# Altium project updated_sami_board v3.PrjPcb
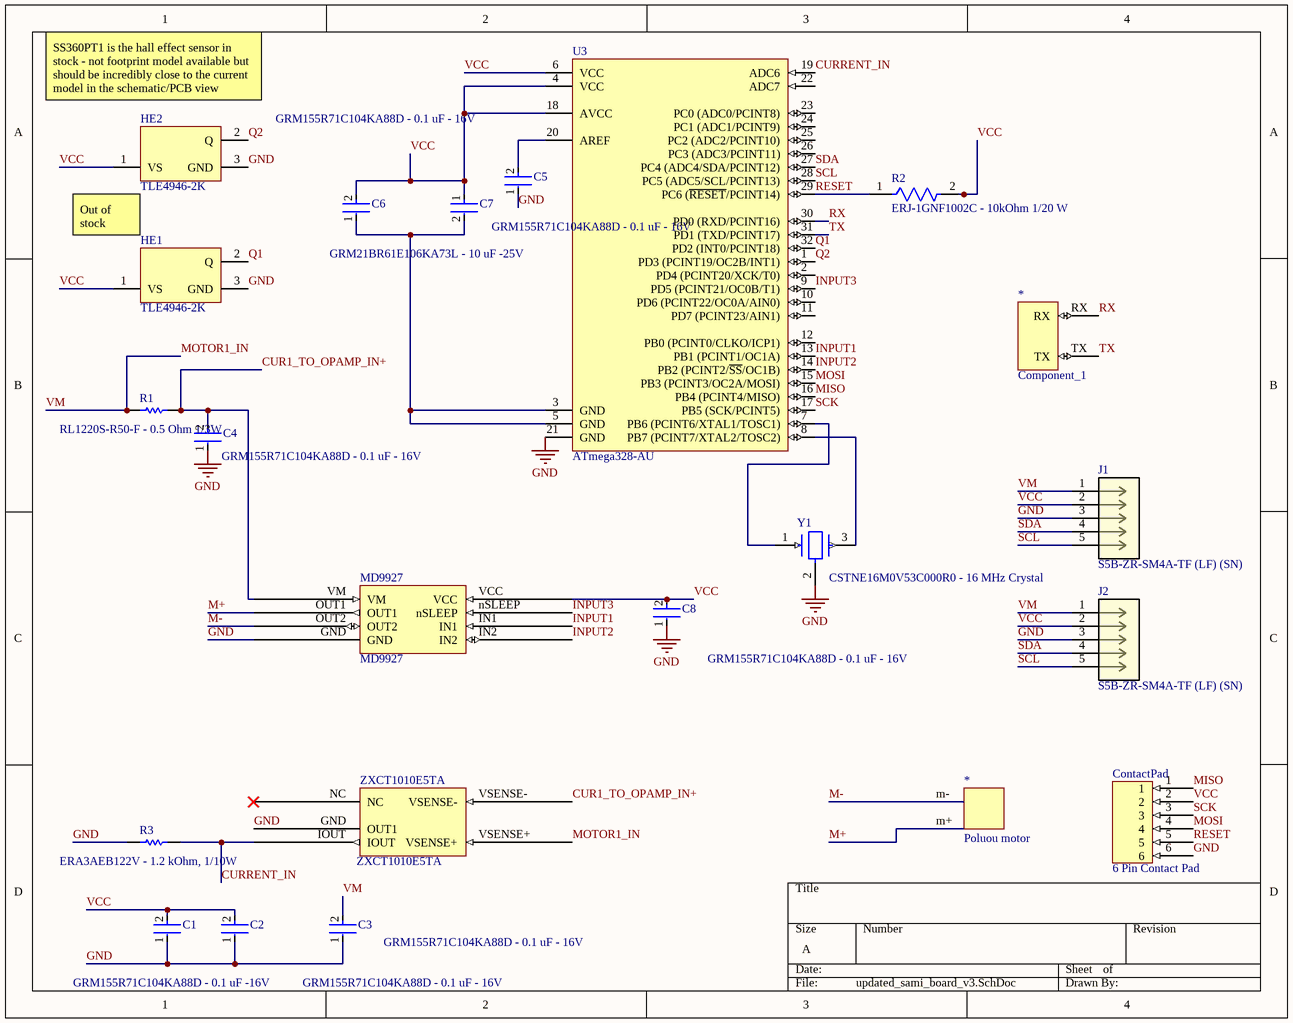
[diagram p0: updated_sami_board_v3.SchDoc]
1 sheet, 22 parts. Net scope: global (net labels, ports and power ports of the same name join across sheets).
Board files: sami_updated_v2.PcbDoc, sami_updated_v3.PcbDoc

## Sheet updated_sami_board_v3.SchDoc
size A; SheetNumber: 1; SheetTotal: 1

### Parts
(Parts that share a designator on the sheet are numbered #1, #2 ... from top to bottom, then left to right.)
*#1  Component_1  [UART Header Pins]
*#2  Poluou motor  [PCBComponent_1]
C1  GRM155R71C104KA88D - 0.1 uF -16V  [FP-GRM15-MFG]
C2  GRM155R71C104KA88D - 0.1 uF - 16V  [FP-GRM15-MFG]
C3  GRM155R71C104KA88D - 0.1 uF - 16V  [FP-GRM15-MFG]
C4  GRM155R71C104KA88D - 0.1 uF - 16V  [FP-GRM15-MFG]
C5  GRM155R71C104KA88D - 0.1 uF - 16V  [FP-GRM15-MFG]
C6  GRM155R71C104KA88D - 0.1 uF - 16V  [FP-GRM15-MFG]
C7  GRM21BR61E106KA73L - 10 uF -25V  [FP-GRM21B-0_15-IPC_C]
C8  GRM155R71C104KA88D - 0.1 uF - 16V  [FP-GRM15-MFG]
ContactPad  6 Pin Contact Pad  [6PinContactPad]
HE1  TLE4946-2K  [INF-PG-SC59_M]
HE2  TLE4946-2K  [INF-PG-SC59_M]
J1  S5B-ZR-SM4A-TF (LF) (SN)  [CONN_S5B-ZR-SM4A-TF_JST]
J2  S5B-ZR-SM4A-TF (LF) (SN)  [CONN_S5B-ZR-SM4A-TF_JST]
MD9927  MD9927  [MD9927]
R1  RL1220S-R50-F - 0.5 Ohm 1/3W  [RESC2013X50X40NL20T20]
R2  ERJ-1GNF1002C - 10kOhm 1/20 W  [FP-ERJ1G-MFG]
R3  ERA3AEB122V - 1.2 kOhm, 1/10W  [RESC1608X55X30ML20T20]
U3  ATmega328-AU  [32A_L]
Y1  CSTNE16M0V53C000R0 - 16 MHz Crystal  [FP-CSTNE16M0V53C000R0-MFG]
ZXCT1010E5TA  ZXCT1010E5TA  [ZXCT1010E5TA]

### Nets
GND: C1.1 C2.1 C3.1 C4.1 C5.1 C8.1 ContactPad.6 HE1.3(GND) HE2.3(GND) J1.3 J2.3 MD9927.GND R3.1 U3.21(GND) Y1.2(GND) ZXCT1010E5TA.GND(OUT1)
CUR1_TO_OPAMP_IN+: C4.2 MD9927.VM R1.2 ZXCT1010E5TA.VSENSE-
CURRENT_IN: R3.2 U3.19(ADC6) ZXCT1010E5TA.IOUT
INPUT1: MD9927.IN1 U3.13(PB1_(PCINT1/OC1A))
INPUT2: MD9927.IN2 U3.14(PB2_(PCINT2/~{SS}/OC1B))
INPUT3: MD9927.nSLEEP U3.9(PD5_(PCINT21/OC0B/T1))
M+: *#2.m+ MD9927.OUT1
M-: *#2.m- MD9927.OUT2
MISO: ContactPad.1 U3.16(PB4_(PCINT4/MISO))
MOSI: ContactPad.4 U3.15(PB3_(PCINT3/OC2A/MOSI))
MOTOR1_IN: C3.2 J1.1 J2.1 R1.1 ZXCT1010E5TA.VSENSE+  [also labelled VM]
Q1: HE1.2(Q) U3.32(PD2_(INT0/PCINT18))
Q2: HE2.2(Q) U3.1(PD3_(PCINT19/OC2B/INT1))
RESET: ContactPad.5 R2.1 U3.29(PC6_(~{RESET}/PCINT14))
RX: *#1.RX U3.30(PD0_(RXD/PCINT16))
SCK: ContactPad.3 U3.17(PB5_(SCK/PCINT5))
SCL: J1.5 J2.5 U3.28(PC5_(ADC5/SCL/PCINT13))
SDA: J1.4 J2.4 U3.27(PC4_(ADC4/SDA/PCINT12))
TX: *#1.TX U3.31(PD1_(TXD/PCINT17))
VCC: C1.2 C2.2 C6.2 C7.1 C8.2 ContactPad.2 HE1.1(VS) HE2.1(VS) J1.2 J2.2 MD9927.VCC R2.2 U3.4(VCC) U3.6(VCC) U3.18(AVCC)
NetC5_2: C5.2 U3.20(AREF)
NetC6_1: C6.1 C7.2 U3.3(GND) U3.5(GND)
NetU3_7: U3.7(PB6_(PCINT6/XTAL1/TOSC1)) Y1.1(Input)
NetU3_8: U3.8(PB7_(PCINT7/XTAL2/TOSC2)) Y1.3(Output)

Not connected (* = marked no-connect by the designer): U3 2(PD4_(PCINT20/XCK/T0)) 10(PD6_(PCINT22/OC0A/AIN0)) 11(PD7_(PCINT23/AIN1)) 12(PB0_(PCINT0/CLKO/ICP1)) 22(ADC7) 23(PC0_(ADC0/PCINT8)) 24(PC1_(ADC1/PCINT9)) 25(PC2_(ADC2/PCINT10)) 26(PC3_(ADC3/PCINT11)); ZXCT1010E5TA NC*

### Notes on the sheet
- (near HE2) SS360PT1 is the hall effect sensor in stock - not footprint model available but should be incredibly close to the current model in the schematic/PCB view
- Out of stock

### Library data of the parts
C1-C6 C8 = CMP-2100-03641-2: CAP CER 0.1UF 16V X7R 0402; Manufacturer: Murata; Standoff Height: 0mm; Tolerance: 10%; Voltage Rating: 16Vdc; Material: Ceramic; Capacitance: 0.10μF; Value: 0.10μF
C7 = CMP-2007-03541-2: Chip Multilayer Ceramic Capacitors for General Purpose, 0805, 10uF, X5R, 15%, 10%, 25V
HE1 HE2 = CMP-1148-00006-1: High Precision Hall Effect Latch, PG-SC59, Reel, Green; Manufacturer: Infineon; Brp (25degreesC) typ: -2Â mT; Target Application: Automotive; Interface: open collector; Chopped Hall Technology: TRUE; Bhyst (25degreesC) max: 4Â mT; Direction Detection: FALSE; Bop (25degreesC) min: 2Â mT
J1 J2 = S5B-ZR-SM4A-TF (LF) (SN): No Description Available; Mfr_Name: JST
R1 = CMP-2001-03168-1: Manufacturer: Susumu
R2 = CMP-2004-03445-2: RES SMD 10K OHM 1% 1/20W 0201; Manufacturer: Panasonic Electronic Components; Power Rating: 0.05W; Voltage Rating: 25V; Resistance: 10kΩ; Automotive Grade: Grade 1; Value: 10kΩ; Temperature Coefficient: 200ppm/°C
R3 = CMP-2000-00897-1: Manufacturer: Panasonic
U3 = CMP-0095-00261-2: 8-bit AVR Microcontroller, 32KB Flash, 1KB EEPROM, 2KB SRAM, 32-pin TQFP, Industrial Grade (-40°C to 85°C)
Y1 = CMP-06057-000009-1: CERAMIC RES 16.0000MHZ 15PF SMD; Impedance: 40R; Frequency Stability: 0.15%; Frequency: 16MHz; Frequency Tolerance: 0.5%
